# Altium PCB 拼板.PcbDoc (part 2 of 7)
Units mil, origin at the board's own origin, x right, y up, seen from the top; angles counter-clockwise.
Board outline 3630.03 x 5330.03 mil, 2 copper layers (Top Layer, Bottom Layer); 416 components, 35 nets, 1936 pads, 800 vias.
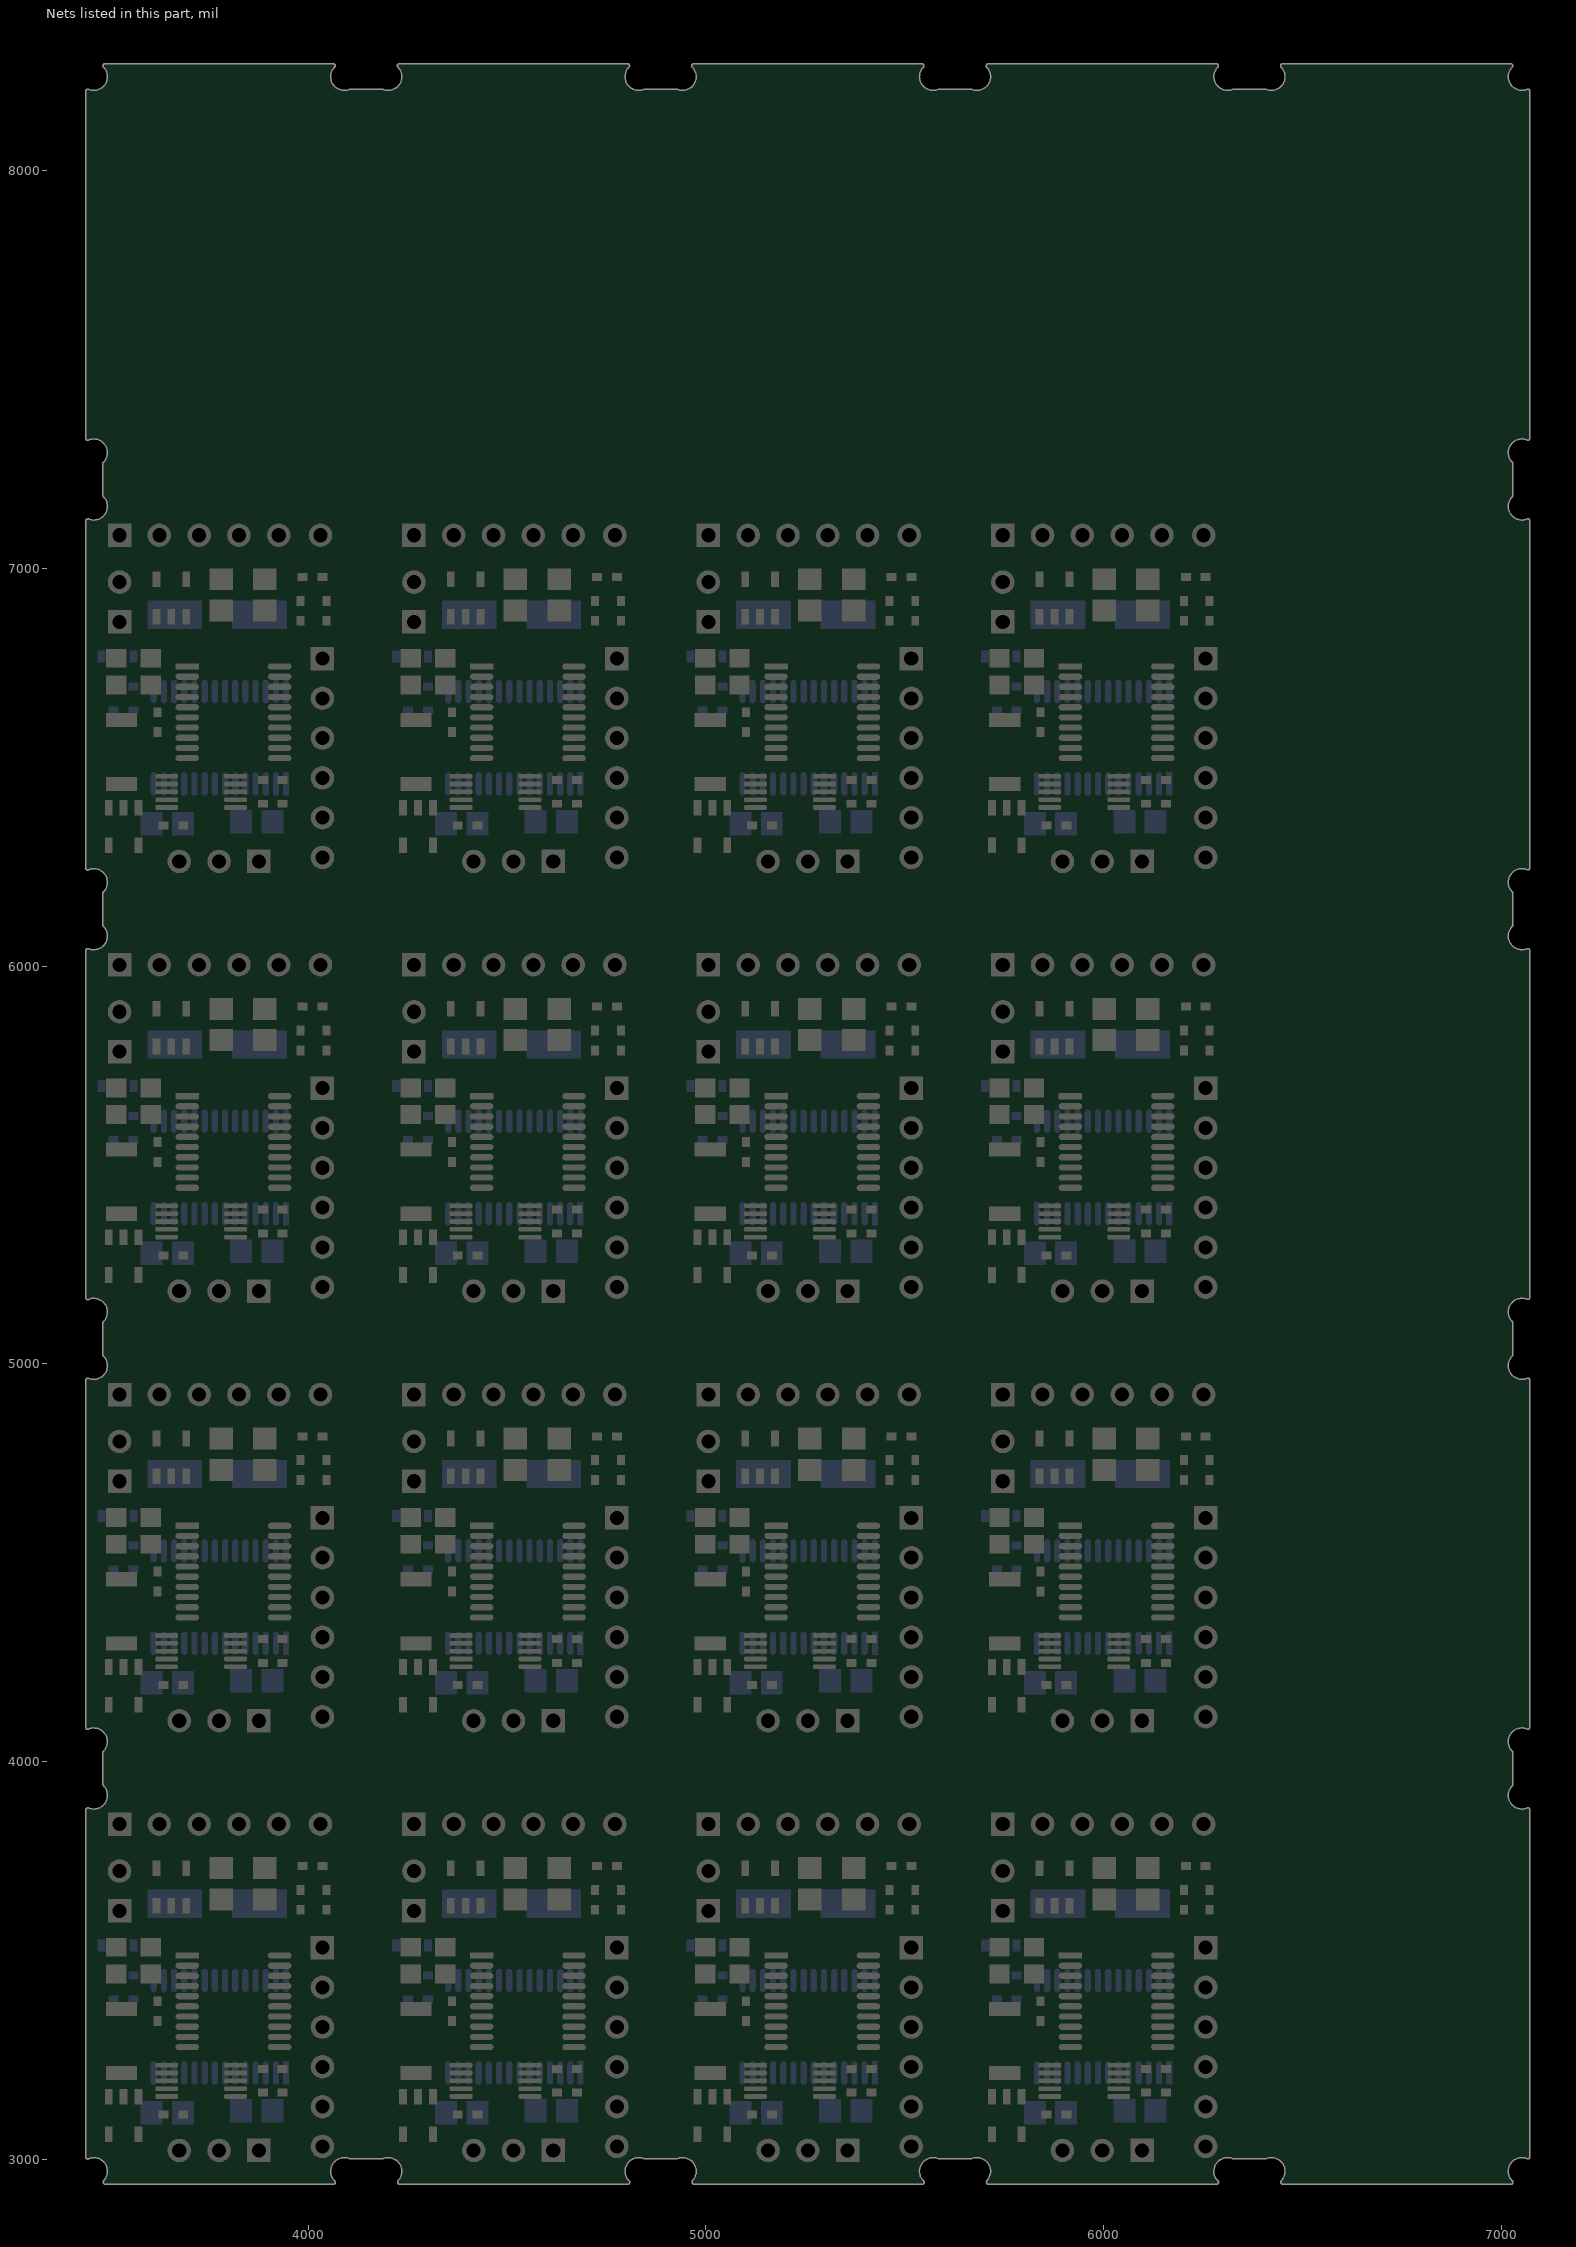
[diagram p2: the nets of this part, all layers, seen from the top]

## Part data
C011_1_1 C011_1_2 C011_1_3 C011_1_4 C011_2_1 C011_2_2 C011_2_3 C011_2_4 C011_3_1 C011_3_2 C011_3_3 C011_3_4 C011_4_1 C011_4_2 C011_4_3 C011_4_4 C021_1_1 C21_1_1 C021_1_2 C21_1_2 C021_1_3 C21_1_3 C021_1_4 C21_1_4 C021_2_1 C21_2_1 C021_2_2 C21_2_2 C021_2_3 C21_2_3 C021_2_4 C21_2_4 C021_3_1 C21_3_1 C021_3_2 C21_3_2 C021_3_3 C21_3_3 C021_3_4 C21_3_4 C021_4_1 C21_4_1 C021_4_2 C21_4_2 C021_4_3 C21_4_3 C021_4_4 C21_4_4 C22_1_1 C22_1_2 C22_1_3 C22_1_4 C22_2_1 C22_2_2 C22_2_3 C22_2_4 C22_3_1 C22_3_2 C22_3_3 C22_3_4 C22_4_1 C22_4_2 C22_4_3 C22_4_4 C23_1_1 C23_1_2 C23_1_3 C23_1_4 C23_2_1 C23_2_2 C23_2_3 C23_2_4 C23_3_1 C23_3_2 C23_3_3 C23_3_4 C23_4_1 C23_4_2 C23_4_3 C23_4_4 C24_1_1 C24_1_2 C24_1_3 C24_1_4 C24_2_1 C24_2_2 C24_2_3 C24_2_4 C24_3_1 C24_3_2 C24_3_3 C24_3_4 C24_4_1 C24_4_2 C24_4_3 C24_4_4 C051_1_1 C051_1_2 C051_1_3 C051_1_4 C051_2_1 C051_2_2 C051_2_3 C051_2_4 C051_3_1 C051_3_2 C051_3_3 C051_3_4 C051_4_1 C051_4_2 C051_4_3 C051_4_4: library part "Cap Semi", "Capacitor (Semiconductor SIM Model)"
D1_1_1 D1_1_2 D1_1_3 D1_1_4 D1_2_1 D1_2_2 D1_2_3 D1_2_4 D1_3_1 D1_3_2 D1_3_3 D1_3_4 D1_4_1 D1_4_2 D1_4_3 D1_4_4 D2_1_1 D2_1_2 D2_1_3 D2_1_4 D2_2_1 D2_2_2 D2_2_3 D2_2_4 D2_3_1 D2_3_2 D2_3_3 D2_3_4 D2_4_1 D2_4_2 D2_4_3 D2_4_4: "Default Diode"
D041_1_1 D041_1_2 D041_1_3 D041_1_4 D041_2_1 D041_2_2 D041_2_3 D041_2_4 D041_3_1 D041_3_2 D041_3_3 D041_3_4 D041_4_1 D041_4_2 D041_4_3 D041_4_4: "Typical RED, GREEN, YELLOW, AMBER GaAs LED"
P1_1_1 P1_1_2 P1_1_3 P1_1_4 P1_2_1 P1_2_2 P1_2_3 P1_2_4 P1_3_1 P1_3_2 P1_3_3 P1_3_4 P1_4_1 P1_4_2 P1_4_3 P1_4_4: "Header, 2-Pin"
P2_1_1 P2_1_2 P2_1_3 P2_1_4 P2_2_1 P2_2_2 P2_2_3 P2_2_4 P2_3_1 P2_3_2 P2_3_3 P2_3_4 P2_4_1 P2_4_2 P2_4_3 P2_4_4 P3_1_1 P3_1_2 P3_1_3 P3_1_4 P3_2_1 P3_2_2 P3_2_3 P3_2_4 P3_3_1 P3_3_2 P3_3_3 P3_3_4 P3_4_1 P3_4_2 P3_4_3 P3_4_4: "Header, 6-Pin"
P4_1_1 P4_1_2 P4_1_3 P4_1_4 P4_2_1 P4_2_2 P4_2_3 P4_2_4 P4_3_1 P4_3_2 P4_3_3 P4_3_4 P4_4_1 P4_4_2 P4_4_3 P4_4_4: "Header, 3-Pin"
R21_1_1 R21_1_2 R21_1_3 R21_1_4 R21_2_1 R21_2_2 R21_2_3 R21_2_4 R21_3_1 R21_3_2 R21_3_3 R21_3_4 R21_4_1 R21_4_2 R21_4_3 R21_4_4 R31_1_1 R31_1_2 R31_1_3 R31_1_4 R31_2_1 R31_2_2 R31_2_3 R31_2_4 R31_3_1 R31_3_2 R31_3_3 R31_3_4 R31_4_1 R31_4_2 R31_4_3 R31_4_4 R32_1_1 R32_1_2 R32_1_3 R32_1_4 R32_2_1 R32_2_2 R32_2_3 R32_2_4 R32_3_1 R32_3_2 R32_3_3 R32_3_4 R32_4_1 R32_4_2 R32_4_3 R32_4_4 R041_1_1 R041_1_2 R041_1_3 R041_1_4 R041_2_1 R041_2_2 R041_2_3 R041_2_4 R041_3_1 R041_3_2 R041_3_3 R041_3_4 R041_4_1 R041_4_2 R041_4_3 R041_4_4: "Resistor"
S051_1_1 S051_1_2 S051_1_3 S051_1_4 S051_2_1 S051_2_2 S051_2_3 S051_2_4 S051_3_1 S051_3_2 S051_3_3 S051_3_4 S051_4_1 S051_4_2 S051_4_3 S051_4_4: "Switch"

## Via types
v1: diameter 24, hole 24, Top Layer to Bottom Layer, 480 vias
v2: diameter 20, hole 10, Top Layer to Bottom Layer, 240 vias
v3: diameter 36, hole 20, Top Layer to Bottom Layer, 48 vias
v4: diameter 32, hole 16, Top Layer to Bottom Layer, 32 vias

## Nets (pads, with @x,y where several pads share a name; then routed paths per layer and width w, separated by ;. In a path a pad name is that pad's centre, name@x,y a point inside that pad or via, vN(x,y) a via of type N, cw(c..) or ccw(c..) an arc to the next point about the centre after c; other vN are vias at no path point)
1V5: 
3V3: 
ADC1_IN4: 
ADC1_IN5: 
GND: 
NetC22_2: 
NetC23_1: 
NetC24_1: 
NetC24_2: 
NetD1_1: 
NetD2_1: 
NetD041_2: 
nFAULT: 
nSLEEP: 
NSRT: 
OSC_EN: 
OSC_IN: 
OUTPUT1: 
OUTPUT2: 
OUTPUT3: 
PGND1: 
PGND3: 
SPI1_CSN: 
SPI1_MISO: 
SPI1_MOSI: 
SPI1_SCK: 
SYS_SWCLK: 
SYS_SWDIO: 
TIM3_CH1: 
TIM3_CH2: 
TIM3_CH3: 
USART1_RX: 
USART1_TX: 
VCC: 
VCC_in: 
pads on no net: C011_1_1.1 C011_1_1.2 C011_1_2.1 C011_1_2.2 C011_1_3.1 C011_1_3.2 C011_1_4.1 C011_1_4.2 C011_2_1.1 C011_2_1.2 C011_2_2.1 C011_2_2.2 C011_2_3.1 C011_2_3.2 C011_2_4.1 C011_2_4.2 C011_3_1.1 C011_3_1.2 C011_3_2.1 C011_3_2.2 C011_3_3.1 C011_3_3.2 C011_3_4.1 C011_3_4.2 C011_4_1.1 C011_4_1.2 C011_4_2.1 C011_4_2.2 C011_4_3.1 C011_4_3.2 C011_4_4.1 C011_4_4.2 C021_1_1.1 C21_1_1.1 C021_1_1.2 C21_1_1.2 C21_1_2.1 C021_1_2.1 C21_1_2.2 C021_1_2.2 C21_1_3.1 C021_1_3.1 C21_1_3.2 C021_1_3.2 C21_1_4.1 C021_1_4.1 C021_1_4.2 C21_1_4.2 C021_2_1.1 C21_2_1.1 C21_2_1.2 C021_2_1.2 C21_2_2.1 C021_2_2.1 C021_2_2.2 C21_2_2.2 C021_2_3.1 C21_2_3.1 C21_2_3.2 C021_2_3.2 C21_2_4.1 C021_2_4.1 C021_2_4.2 C21_2_4.2 C21_3_1.1 C021_3_1.1 C021_3_1.2 C21_3_1.2 C021_3_2.1 C21_3_2.1 C21_3_2.2 C021_3_2.2 C21_3_3.1 C021_3_3.1 C21_3_3.2 C021_3_3.2 C21_3_4.1 C021_3_4.1 C021_3_4.2 C21_3_4.2 C21_4_1.1 C021_4_1.1 C021_4_1.2 C21_4_1.2 C021_4_2.1 C21_4_2.1 C021_4_2.2 C21_4_2.2 C021_4_3.1 C21_4_3.1 C21_4_3.2 C021_4_3.2 C021_4_4.1 C21_4_4.1 C21_4_4.2 C021_4_4.2 C22_1_1.1 C22_1_1.2 C22_1_2.1 C22_1_2.2 C22_1_3.1 C22_1_3.2 C22_1_4.1 C22_1_4.2 C22_2_1.1 C22_2_1.2 C22_2_2.1 C22_2_2.2 C22_2_3.1 C22_2_3.2 C22_2_4.1 C22_2_4.2 C22_3_1.1 C22_3_1.2 C22_3_2.1 C22_3_2.2 C22_3_3.1 C22_3_3.2 C22_3_4.1 C22_3_4.2 C22_4_1.1 C22_4_1.2 C22_4_2.1 C22_4_2.2 C22_4_3.1 C22_4_3.2 C22_4_4.1 C22_4_4.2 C23_1_1.1 C23_1_1.2 C23_1_2.1 C23_1_2.2 C23_1_3.1 C23_1_3.2 C23_1_4.1 C23_1_4.2 C23_2_1.1 C23_2_1.2 C23_2_2.1 C23_2_2.2 C23_2_3.1 C23_2_3.2 C23_2_4.1 C23_2_4.2 C23_3_1.1 C23_3_1.2 C23_3_2.1 C23_3_2.2 C23_3_3.1 C23_3_3.2 C23_3_4.1 C23_3_4.2 C23_4_1.1 C23_4_1.2 C23_4_2.1 C23_4_2.2 C23_4_3.1 C23_4_3.2 C23_4_4.1 C23_4_4.2 C24_1_1.1 C24_1_1.2 C24_1_2.1 C24_1_2.2 C24_1_3.1 C24_1_3.2 C24_1_4.1 C24_1_4.2 C24_2_1.1 C24_2_1.2 C24_2_2.1 C24_2_2.2 C24_2_3.1 C24_2_3.2 C24_2_4.1 C24_2_4.2 C24_3_1.1 C24_3_1.2 C24_3_2.1 C24_3_2.2 C24_3_3.1 C24_3_3.2 C24_3_4.1 C24_3_4.2 C24_4_1.1 C24_4_1.2 C24_4_2.1 C24_4_2.2 C24_4_3.1 C24_4_3.2 C24_4_4.1 C24_4_4.2 C051_1_1.1 C051_1_1.2 C051_1_2.1 C051_1_2.2 C051_1_3.1 C051_1_3.2 C051_1_4.1 C051_1_4.2 C051_2_1.1 C051_2_1.2 C051_2_2.1 C051_2_2.2 C051_2_3.1 C051_2_3.2 C051_2_4.1 C051_2_4.2 C051_3_1.1 C051_3_1.2 C051_3_2.1 C051_3_2.2 C051_3_3.1 C051_3_3.2 C051_3_4.1 C051_3_4.2 C051_4_1.1 C051_4_1.2 C051_4_2.1 C051_4_2.2 C051_4_3.1 C051_4_3.2 C051_4_4.1 C051_4_4.2 con21_1_1.1 con21_1_1.2 con21_1_2.1 con21_1_2.2 con21_1_3.1 con21_1_3.2 con21_1_4.1 con21_1_4.2 con21_2_1.1 con21_2_1.2 con21_2_2.1 con21_2_2.2 con21_2_3.1 con21_2_3.2 con21_2_4.1 con21_2_4.2 con21_3_1.1 con21_3_1.2 con21_3_2.1 con21_3_2.2 con21_3_3.1 con21_3_3.2 con21_3_4.1 con21_3_4.2 con21_4_1.1 con21_4_1.2 con21_4_2.1 con21_4_2.2 con21_4_3.1 con21_4_3.2 con21_4_4.1 con21_4_4.2 D1_1_1.1 D1_1_1.2 D1_1_2.1 D1_1_2.2 D1_1_3.1 D1_1_3.2 D1_1_4.1 D1_1_4.2 D1_2_1.1 D1_2_1.2 D1_2_2.1 D1_2_2.2 D1_2_3.1 D1_2_3.2 D1_2_4.1 D1_2_4.2 D1_3_1.1 D1_3_1.2 D1_3_2.1 D1_3_2.2 D1_3_3.1 D1_3_3.2 D1_3_4.1 D1_3_4.2 D1_4_1.1 D1_4_1.2 D1_4_2.1 D1_4_2.2 D1_4_3.1 D1_4_3.2 D1_4_4.1 D1_4_4.2 D2_1_1.1 D2_1_1.2 D2_1_2.1 D2_1_2.2 D2_1_3.1 D2_1_3.2 D2_1_4.1 D2_1_4.2 D2_2_1.1 D2_2_1.2 D2_2_2.1 D2_2_2.2 D2_2_3.1 D2_2_3.2 D2_2_4.1 D2_2_4.2 D2_3_1.1 D2_3_1.2 D2_3_2.1 D2_3_2.2 D2_3_3.1 D2_3_3.2 D2_3_4.1 D2_3_4.2 D2_4_1.1 D2_4_1.2 D2_4_2.1 D2_4_2.2 D2_4_3.1 D2_4_3.2 D2_4_4.1 D2_4_4.2 D041_1_1.1 D041_1_1.2 D041_1_2.1 D041_1_2.2 D041_1_3.1 D041_1_3.2 D041_1_4.1 D041_1_4.2 D041_2_1.1 D041_2_1.2 D041_2_2.1 D041_2_2.2 D041_2_3.1 D041_2_3.2 D041_2_4.1 D041_2_4.2 D041_3_1.1 D041_3_1.2 D041_3_2.1 D041_3_2.2 D041_3_3.1 D041_3_3.2 D041_3_4.1 D041_3_4.2 D041_4_1.1 D041_4_1.2 D041_4_2.1 D041_4_2.2 D041_4_3.1 D041_4_3.2 D041_4_4.1 D041_4_4.2 P1_1_1.1 P1_1_1.2 P1_1_2.1 P1_1_2.2 P1_1_3.1 P1_1_3.2 P1_1_4.1 P1_1_4.2 P1_2_1.1 P1_2_1.2 P1_2_2.1 P1_2_2.2 P1_2_3.1 P1_2_3.2 P1_2_4.1 P1_2_4.2 P1_3_1.1 P1_3_1.2 P1_3_2.1 P1_3_2.2 P1_3_3.1 P1_3_3.2 P1_3_4.1 P1_3_4.2 P1_4_1.1 P1_4_1.2 P1_4_2.1 P1_4_2.2 P1_4_3.1 P1_4_3.2 P1_4_4.1 P1_4_4.2 P2_1_1.1 P2_1_1.2 P2_1_1.3 P2_1_1.4 P2_1_1.5 P2_1_1.6 P2_1_2.1 P2_1_2.2 P2_1_2.3 P2_1_2.4 P2_1_2.5 P2_1_2.6 P2_1_3.1 P2_1_3.2 P2_1_3.3 P2_1_3.4 P2_1_3.5 P2_1_3.6 P2_1_4.1 P2_1_4.2 P2_1_4.3 P2_1_4.4 P2_1_4.5 P2_1_4.6 P2_2_1.1 P2_2_1.2 P2_2_1.3 P2_2_1.4 P2_2_1.5 P2_2_1.6 P2_2_2.1 P2_2_2.2 P2_2_2.3 P2_2_2.4 P2_2_2.5 P2_2_2.6 P2_2_3.1 P2_2_3.2 P2_2_3.3 P2_2_3.4 P2_2_3.5 P2_2_3.6 P2_2_4.1 P2_2_4.2 P2_2_4.3 P2_2_4.4 P2_2_4.5 P2_2_4.6 P2_3_1.1 P2_3_1.2 P2_3_1.3 P2_3_1.4 P2_3_1.5 P2_3_1.6 P2_3_2.1 P2_3_2.2 P2_3_2.3 P2_3_2.4 P2_3_2.5 P2_3_2.6 P2_3_3.1 P2_3_3.2 P2_3_3.3 P2_3_3.4 P2_3_3.5 P2_3_3.6 P2_3_4.1 P2_3_4.2 P2_3_4.3 P2_3_4.4 P2_3_4.5 P2_3_4.6 P2_4_1.1 P2_4_1.2 P2_4_1.3 P2_4_1.4 P2_4_1.5 P2_4_1.6 P2_4_2.1 P2_4_2.2 P2_4_2.3 P2_4_2.4 P2_4_2.5 P2_4_2.6 P2_4_3.1 P2_4_3.2 P2_4_3.3 P2_4_3.4 P2_4_3.5 P2_4_3.6 P2_4_4.1 P2_4_4.2 P2_4_4.3 P2_4_4.4 P2_4_4.5 P2_4_4.6 P3_1_1.1 P3_1_1.2 P3_1_1.3 P3_1_1.4 P3_1_1.5 P3_1_1.6 P3_1_2.1 P3_1_2.2 P3_1_2.3 P3_1_2.4 P3_1_2.5 P3_1_2.6 P3_1_3.1 P3_1_3.2 P3_1_3.3 P3_1_3.4 P3_1_3.5 P3_1_3.6 P3_1_4.1 P3_1_4.2 P3_1_4.3 P3_1_4.4 P3_1_4.5 P3_1_4.6 P3_2_1.1 P3_2_1.2 P3_2_1.3 P3_2_1.4 P3_2_1.5 P3_2_1.6 P3_2_2.1 P3_2_2.2 P3_2_2.3 P3_2_2.4 P3_2_2.5 P3_2_2.6 P3_2_3.1 P3_2_3.2 P3_2_3.3 P3_2_3.4 P3_2_3.5 P3_2_3.6 P3_2_4.1 P3_2_4.2 P3_2_4.3 P3_2_4.4 P3_2_4.5 P3_2_4.6 P3_3_1.1 P3_3_1.2 P3_3_1.3 P3_3_1.4 P3_3_1.5 P3_3_1.6 P3_3_2.1 P3_3_2.2 P3_3_2.3 P3_3_2.4 P3_3_2.5 P3_3_2.6 P3_3_3.1 P3_3_3.2 P3_3_3.3 P3_3_3.4 P3_3_3.5 P3_3_3.6 P3_3_4.1 P3_3_4.2 P3_3_4.3 P3_3_4.4 P3_3_4.5 P3_3_4.6 P3_4_1.1 P3_4_1.2 P3_4_1.3 P3_4_1.4 P3_4_1.5 P3_4_1.6 P3_4_2.1 P3_4_2.2 P3_4_2.3 P3_4_2.4 P3_4_2.5 P3_4_2.6 P3_4_3.1 P3_4_3.2 P3_4_3.3 P3_4_3.4 P3_4_3.5 P3_4_3.6 P3_4_4.1 P3_4_4.2 P3_4_4.3 P3_4_4.4 P3_4_4.5 P3_4_4.6 P4_1_1.1 P4_1_1.2 P4_1_1.3 P4_1_2.1 P4_1_2.2 P4_1_2.3 P4_1_3.1 P4_1_3.2 P4_1_3.3 P4_1_4.1 P4_1_4.2 P4_1_4.3 P4_2_1.1 P4_2_1.2 P4_2_1.3 P4_2_2.1 P4_2_2.2 P4_2_2.3 P4_2_3.1 P4_2_3.2 P4_2_3.3 P4_2_4.1 P4_2_4.2 P4_2_4.3 P4_3_1.1 P4_3_1.2 P4_3_1.3 P4_3_2.1 P4_3_2.2 P4_3_2.3 P4_3_3.1 P4_3_3.2 P4_3_3.3 P4_3_4.1 P4_3_4.2 P4_3_4.3 P4_4_1.1 P4_4_1.2 P4_4_1.3 P4_4_2.1 P4_4_2.2 P4_4_2.3 P4_4_3.1 P4_4_3.2 P4_4_3.3 P4_4_4.1 P4_4_4.2 P4_4_4.3 R21_1_1.1 R21_1_1.2 R21_1_2.1 R21_1_2.2 R21_1_3.1 R21_1_3.2 R21_1_4.1 R21_1_4.2 R21_2_1.1 R21_2_1.2 R21_2_2.1 R21_2_2.2 R21_2_3.1 R21_2_3.2 R21_2_4.1 R21_2_4.2 R21_3_1.1 R21_3_1.2 R21_3_2.1 R21_3_2.2 R21_3_3.1 R21_3_3.2 R21_3_4.1 R21_3_4.2 R21_4_1.1 R21_4_1.2 R21_4_2.1 R21_4_2.2 R21_4_3.1 R21_4_3.2 R21_4_4.1 R21_4_4.2 R31_1_1.1 R31_1_1.2 R31_1_2.1 R31_1_2.2 R31_1_3.1 R31_1_3.2 R31_1_4.1 R31_1_4.2 R31_2_1.1 R31_2_1.2 R31_2_2.1 R31_2_2.2 R31_2_3.1 R31_2_3.2 R31_2_4.1 R31_2_4.2 R31_3_1.1 R31_3_1.2 R31_3_2.1 R31_3_2.2 R31_3_3.1 R31_3_3.2 R31_3_4.1 R31_3_4.2 R31_4_1.1 R31_4_1.2 R31_4_2.1 R31_4_2.2 R31_4_3.1 R31_4_3.2 R31_4_4.1 R31_4_4.2 R32_1_1.1 R32_1_1.2 R32_1_2.1 R32_1_2.2 R32_1_3.1 R32_1_3.2 R32_1_4.1 R32_1_4.2 R32_2_1.1 R32_2_1.2 R32_2_2.1 R32_2_2.2 R32_2_3.1 R32_2_3.2 R32_2_4.1 R32_2_4.2 R32_3_1.1 R32_3_1.2 R32_3_2.1 R32_3_2.2 R32_3_3.1 R32_3_3.2 R32_3_4.1 R32_3_4.2 R32_4_1.1 R32_4_1.2 R32_4_2.1 R32_4_2.2 R32_4_3.1 R32_4_3.2 R32_4_4.1 R32_4_4.2 R041_1_1.1 R041_1_1.2 R041_1_2.1 R041_1_2.2 R041_1_3.1 R041_1_3.2 R041_1_4.1 R041_1_4.2 R041_2_1.1 R041_2_1.2 R041_2_2.1 R041_2_2.2 R041_2_3.1 R041_2_3.2 R041_2_4.1 R041_2_4.2 R041_3_1.1 R041_3_1.2 R041_3_2.1 R041_3_2.2 R041_3_3.1 R041_3_3.2 R041_3_4.1 R041_3_4.2 R041_4_1.1 R041_4_1.2 R041_4_2.1 R041_4_2.2 R041_4_3.1 R041_4_3.2 R041_4_4.1 R041_4_4.2 S051_1_1.1 S051_1_1.2 S051_1_2.1 S051_1_2.2 S051_1_3.1 S051_1_3.2 S051_1_4.1 S051_1_4.2 S051_2_1.1 S051_2_1.2 S051_2_2.1 S051_2_2.2 S051_2_3.1 S051_2_3.2 S051_2_4.1 S051_2_4.2 S051_3_1.1 S051_3_1.2 S051_3_2.1 S051_3_2.2 S051_3_3.1 S051_3_3.2 S051_3_4.1 S051_3_4.2 S051_4_1.1 S051_4_1.2 S051_4_2.1 S051_4_2.2 S051_4_3.1 S051_4_3.2 S051_4_4.1 S051_4_4.2 U1_1_1.1 U01_1_1.1 U1_1_1.2 U01_1_1.2 U01_1_1.3 U1_1_1.3 U1_1_1.4 U01_1_1.4 U01_1_1.5 U1_1_1.5 U1_1_1.6 U1_1_1.7 U1_1_1.8 U1_1_1.9 U1_1_1.10 U1_1_1.11 U1_1_1.12 U1_1_1.13 U1_1_1.14 U1_1_1.15 U1_1_1.16 U1_1_1.17 U1_1_1.18 U1_1_1.19 U1_1_1.20 U1_1_2.1 U01_1_2.1 U01_1_2.2 U1_1_2.2 U01_1_2.3 U1_1_2.3 U01_1_2.4 U1_1_2.4 U01_1_2.5 U1_1_2.5 U1_1_2.6 U1_1_2.7 U1_1_2.8 U1_1_2.9 U1_1_2.10 U1_1_2.11 U1_1_2.12 U1_1_2.13 U1_1_2.14 U1_1_2.15 U1_1_2.16 U1_1_2.17 U1_1_2.18 U1_1_2.19 U1_1_2.20 U1_1_3.1 U01_1_3.1 U1_1_3.2 U01_1_3.2 U01_1_3.3 U1_1_3.3 U1_1_3.4 U01_1_3.4 U01_1_3.5 U1_1_3.5 U1_1_3.6 U1_1_3.7 U1_1_3.8 U1_1_3.9 U1_1_3.10 U1_1_3.11 U1_1_3.12 U1_1_3.13 U1_1_3.14 U1_1_3.15 U1_1_3.16 U1_1_3.17 U1_1_3.18 U1_1_3.19 U1_1_3.20 U1_1_4.1 U01_1_4.1 U01_1_4.2 U1_1_4.2 U01_1_4.3 U1_1_4.3 U1_1_4.4 U01_1_4.4 U01_1_4.5 U1_1_4.5 U1_1_4.6 U1_1_4.7 U1_1_4.8 U1_1_4.9 U1_1_4.10 U1_1_4.11 U1_1_4.12 U1_1_4.13 U1_1_4.14 U1_1_4.15 U1_1_4.16 U1_1_4.17 U1_1_4.18 U1_1_4.19 U1_1_4.20 U01_2_1.1 U1_2_1.1 U01_2_1.2 U1_2_1.2 U1_2_1.3 U01_2_1.3 U1_2_1.4 U01_2_1.4 U01_2_1.5 U1_2_1.5 U1_2_1.6 U1_2_1.7 U1_2_1.8 U1_2_1.9 U1_2_1.10 U1_2_1.11 U1_2_1.12 U1_2_1.13 U1_2_1.14 U1_2_1.15 U1_2_1.16 U1_2_1.17 U1_2_1.18 U1_2_1.19 U1_2_1.20 U01_2_2.1 U1_2_2.1 U01_2_2.2 U1_2_2.2 U01_2_2.3 U1_2_2.3 U1_2_2.4 U01_2_2.4 U01_2_2.5 U1_2_2.5 U1_2_2.6 U1_2_2.7 U1_2_2.8 U1_2_2.9 U1_2_2.10 U1_2_2.11 U1_2_2.12 U1_2_2.13 U1_2_2.14 U1_2_2.15 U1_2_2.16 U1_2_2.17 U1_2_2.18 U1_2_2.19 U1_2_2.20 U01_2_3.1 U1_2_3.1 U1_2_3.2 U01_2_3.2 U01_2_3.3 U1_2_3.3 U1_2_3.4 U01_2_3.4 U01_2_3.5 U1_2_3.5 U1_2_3.6 U1_2_3.7 U1_2_3.8 U1_2_3.9 U1_2_3.10 U1_2_3.11 U1_2_3.12 U1_2_3.13 U1_2_3.14 U1_2_3.15 U1_2_3.16 U1_2_3.17 U1_2_3.18 U1_2_3.19 U1_2_3.20 U1_2_4.1 U01_2_4.1 U01_2_4.2 U1_2_4.2 U1_2_4.3 U01_2_4.3 U01_2_4.4 U1_2_4.4 U1_2_4.5 U01_2_4.5 U1_2_4.6 U1_2_4.7 U1_2_4.8 U1_2_4.9 U1_2_4.10 U1_2_4.11 U1_2_4.12 U1_2_4.13 U1_2_4.14 U1_2_4.15 U1_2_4.16 U1_2_4.17 U1_2_4.18 U1_2_4.19 U1_2_4.20 U1_3_1.1 U01_3_1.1 U1_3_1.2 U01_3_1.2 U1_3_1.3 U01_3_1.3 U01_3_1.4 U1_3_1.4 U01_3_1.5 U1_3_1.5 U1_3_1.6 U1_3_1.7 U1_3_1.8 U1_3_1.9 U1_3_1.10 U1_3_1.11 U1_3_1.12 U1_3_1.13 U1_3_1.14 U1_3_1.15 U1_3_1.16 U1_3_1.17 U1_3_1.18 U1_3_1.19 U1_3_1.20 U01_3_2.1 U1_3_2.1 U1_3_2.2 U01_3_2.2 U1_3_2.3 U01_3_2.3 U01_3_2.4 U1_3_2.4 U1_3_2.5 U01_3_2.5 U1_3_2.6 U1_3_2.7 U1_3_2.8 U1_3_2.9 U1_3_2.10 U1_3_2.11 U1_3_2.12 U1_3_2.13 U1_3_2.14 U1_3_2.15 U1_3_2.16 U1_3_2.17 U1_3_2.18 U1_3_2.19 U1_3_2.20 U1_3_3.1 U01_3_3.1 U1_3_3.2 U01_3_3.2 U01_3_3.3 U1_3_3.3 U1_3_3.4 U01_3_3.4 U01_3_3.5 U1_3_3.5 U1_3_3.6 U1_3_3.7 U1_3_3.8 U1_3_3.9 U1_3_3.10 U1_3_3.11 U1_3_3.12 U1_3_3.13 U1_3_3.14 U1_3_3.15 U1_3_3.16 U1_3_3.17 U1_3_3.18 U1_3_3.19 U1_3_3.20 U01_3_4.1 U1_3_4.1 U1_3_4.2 U01_3_4.2 U1_3_4.3 U01_3_4.3 U1_3_4.4 U01_3_4.4 U01_3_4.5 U1_3_4.5 U1_3_4.6 U1_3_4.7 U1_3_4.8 U1_3_4.9 U1_3_4.10 U1_3_4.11 U1_3_4.12 U1_3_4.13 U1_3_4.14 U1_3_4.15 U1_3_4.16 U1_3_4.17 U1_3_4.18 U1_3_4.19 U1_3_4.20 U01_4_1.1 U1_4_1.1 U1_4_1.2 U01_4_1.2 U1_4_1.3 U01_4_1.3 U01_4_1.4 U1_4_1.4 U01_4_1.5 U1_4_1.5 U1_4_1.6 U1_4_1.7 U1_4_1.8 U1_4_1.9 U1_4_1.10 U1_4_1.11 U1_4_1.12 U1_4_1.13 U1_4_1.14 U1_4_1.15 U1_4_1.16 U1_4_1.17 U1_4_1.18 U1_4_1.19 U1_4_1.20 U1_4_2.1 U01_4_2.1 U01_4_2.2 U1_4_2.2 U1_4_2.3 U01_4_2.3 U1_4_2.4 U01_4_2.4 U1_4_2.5 U01_4_2.5 U1_4_2.6 U1_4_2.7 U1_4_2.8 U1_4_2.9 U1_4_2.10 U1_4_2.11 U1_4_2.12 U1_4_2.13 U1_4_2.14 U1_4_2.15 U1_4_2.16 U1_4_2.17 U1_4_2.18 U1_4_2.19 U1_4_2.20 U01_4_3.1 U1_4_3.1 U01_4_3.2 U1_4_3.2 U01_4_3.3 U1_4_3.3 U01_4_3.4 U1_4_3.4 U01_4_3.5 U1_4_3.5 U1_4_3.6 U1_4_3.7 U1_4_3.8 U1_4_3.9 U1_4_3.10 U1_4_3.11 U1_4_3.12 U1_4_3.13 U1_4_3.14 U1_4_3.15 U1_4_3.16 U1_4_3.17 U1_4_3.18 U1_4_3.19 U1_4_3.20 U01_4_4.1 U1_4_4.1 U01_4_4.2 U1_4_4.2 U01_4_4.3 U1_4_4.3 U01_4_4.4 U1_4_4.4 U01_4_4.5 U1_4_4.5 U1_4_4.6 U1_4_4.7 U1_4_4.8 U1_4_4.9 U1_4_4.10 U1_4_4.11 U1_4_4.12 U1_4_4.13 U1_4_4.14 U1_4_4.15 U1_4_4.16 U1_4_4.17 U1_4_4.18 U1_4_4.19 U1_4_4.20 u02_1_1.1 U02_1_1.1 U2_1_1.1 u02_1_1.2 U2_1_1.2 U02_1_1.2 U2_1_1.3 U02_1_1.3 u02_1_1.3 U02_1_1.4 u02_1_1.4 U2_1_1.4 U2_1_1.5 u02_1_1.5 U2_1_1.6 U2_1_1.7 U2_1_1.8 U2_1_1.9 U2_1_1.10 U2_1_1.11 U2_1_1.12 U2_1_1.13 U2_1_1.14 U2_1_1.15 U2_1_1.16 U2_1_1.17 U2_1_1.18 U2_1_1.19 U2_1_1.20 U2_1_1.21 U2_1_1.22 U2_1_1.23 U2_1_1.24 U2_1_1.25 U2_1_1.26 U2_1_1.27 U2_1_1.28 U2_1_2.1 U02_1_2.1 u02_1_2.1 U2_1_2.2 U02_1_2.2 u02_1_2.2 U02_1_2.3 U2_1_2.3 u02_1_2.3 u02_1_2.4 U02_1_2.4 U2_1_2.4 u02_1_2.5 U2_1_2.5 U2_1_2.6 U2_1_2.7 U2_1_2.8 U2_1_2.9 U2_1_2.10 U2_1_2.11 U2_1_2.12 U2_1_2.13 U2_1_2.14 U2_1_2.15 U2_1_2.16 U2_1_2.17 U2_1_2.18 U2_1_2.19 U2_1_2.20 U2_1_2.21 U2_1_2.22 U2_1_2.23 U2_1_2.24 U2_1_2.25 U2_1_2.26 U2_1_2.27 U2_1_2.28 U02_1_3.1 u02_1_3.1 U2_1_3.1 u02_1_3.2 U02_1_3.2 U2_1_3.2 u02_1_3.3 U2_1_3.3 U02_1_3.3 U02_1_3.4 U2_1_3.4 u02_1_3.4 U2_1_3.5 u02_1_3.5 U2_1_3.6 U2_1_3.7 U2_1_3.8 U2_1_3.9 U2_1_3.10 U2_1_3.11 U2_1_3.12 U2_1_3.13 U2_1_3.14 U2_1_3.15 U2_1_3.16 U2_1_3.17 U2_1_3.18 U2_1_3.19 U2_1_3.20 U2_1_3.21 U2_1_3.22 U2_1_3.23 U2_1_3.24 U2_1_3.25 U2_1_3.26 U2_1_3.27 U2_1_3.28 u02_1_4.1 U02_1_4.1 U2_1_4.1 U02_1_4.2 U2_1_4.2 u02_1_4.2 u02_1_4.3 U02_1_4.3 U2_1_4.3 u02_1_4.4 U2_1_4.4 U02_1_4.4 U2_1_4.5 u02_1_4.5 U2_1_4.6 U2_1_4.7 U2_1_4.8 U2_1_4.9 U2_1_4.10 U2_1_4.11 U2_1_4.12 U2_1_4.13 U2_1_4.14 U2_1_4.15 U2_1_4.16 U2_1_4.17 U2_1_4.18 U2_1_4.19 U2_1_4.20 U2_1_4.21 U2_1_4.22 U2_1_4.23 U2_1_4.24 U2_1_4.25 U2_1_4.26 U2_1_4.27 U2_1_4.28 U02_2_1.1 U2_2_1.1 u02_2_1.1 u02_2_1.2 U02_2_1.2 U2_2_1.2 u02_2_1.3 U02_2_1.3 U2_2_1.3 U02_2_1.4 u02_2_1.4 U2_2_1.4 u02_2_1.5 U2_2_1.5 U2_2_1.6 U2_2_1.7 U2_2_1.8 U2_2_1.9 U2_2_1.10 U2_2_1.11 U2_2_1.12 U2_2_1.13 U2_2_1.14 U2_2_1.15 U2_2_1.16 U2_2_1.17 U2_2_1.18 U2_2_1.19 U2_2_1.20 U2_2_1.21 U2_2_1.22 U2_2_1.23 U2_2_1.24 U2_2_1.25 U2_2_1.26 U2_2_1.27 U2_2_1.28 U2_2_2.1 U02_2_2.1 u02_2_2.1 U2_2_2.2 U02_2_2.2 u02_2_2.2 U02_2_2.3 U2_2_2.3 u02_2_2.3 u02_2_2.4 U02_2_2.4 U2_2_2.4 U2_2_2.5 u02_2_2.5 U2_2_2.6 U2_2_2.7 U2_2_2.8 U2_2_2.9 U2_2_2.10 U2_2_2.11 U2_2_2.12 U2_2_2.13 U2_2_2.14 U2_2_2.15 U2_2_2.16 U2_2_2.17 U2_2_2.18 U2_2_2.19 U2_2_2.20 U2_2_2.21 U2_2_2.22 U2_2_2.23 U2_2_2.24 U2_2_2.25 U2_2_2.26 U2_2_2.27 U2_2_2.28 U2_2_3.1 u02_2_3.1 U02_2_3.1 U2_2_3.2 u02_2_3.2 U02_2_3.2 U02_2_3.3 u02_2_3.3 U2_2_3.3 u02_2_3.4 U02_2_3.4 U2_2_3.4 u02_2_3.5 U2_2_3.5 U2_2_3.6 U2_2_3.7 U2_2_3.8 U2_2_3.9 U2_2_3.10 U2_2_3.11 U2_2_3.12 U2_2_3.13 U2_2_3.14 U2_2_3.15 U2_2_3.16 U2_2_3.17 U2_2_3.18 U2_2_3.19 U2_2_3.20 U2_2_3.21 U2_2_3.22 U2_2_3.23 U2_2_3.24 U2_2_3.25 U2_2_3.26 U2_2_3.27 U2_2_3.28 U02_2_4.1 U2_2_4.1 u02_2_4.1 U2_2_4.2 U02_2_4.2 u02_2_4.2 U2_2_4.3 u02_2_4.3 U02_2_4.3 U2_2_4.4 u02_2_4.4 U02_2_4.4 u02_2_4.5 U2_2_4.5 U2_2_4.6 U2_2_4.7 U2_2_4.8 U2_2_4.9 U2_2_4.10 U2_2_4.11 U2_2_4.12 U2_2_4.13 U2_2_4.14 U2_2_4.15 U2_2_4.16 U2_2_4.17 U2_2_4.18 U2_2_4.19 U2_2_4.20 U2_2_4.21 U2_2_4.22 U2_2_4.23 U2_2_4.24 U2_2_4.25 U2_2_4.26 U2_2_4.27 U2_2_4.28 u02_3_1.1 U02_3_1.1 U2_3_1.1 U2_3_1.2 u02_3_1.2 U02_3_1.2 U2_3_1.3 U02_3_1.3 u02_3_1.3 U2_3_1.4 u02_3_1.4 U02_3_1.4 u02_3_1.5 U2_3_1.5 U2_3_1.6 U2_3_1.7 U2_3_1.8 U2_3_1.9 U2_3_1.10 U2_3_1.11 U2_3_1.12 U2_3_1.13 U2_3_1.14 U2_3_1.15 U2_3_1.16 U2_3_1.17 U2_3_1.18 U2_3_1.19 U2_3_1.20 U2_3_1.21 U2_3_1.22 U2_3_1.23 U2_3_1.24 U2_3_1.25 U2_3_1.26 U2_3_1.27 U2_3_1.28 U2_3_2.1 u02_3_2.1 U02_3_2.1 u02_3_2.2 U2_3_2.2 U02_3_2.2 u02_3_2.3 U02_3_2.3 U2_3_2.3 U02_3_2.4 u02_3_2.4 U2_3_2.4 u02_3_2.5 U2_3_2.5 U2_3_2.6 U2_3_2.7 U2_3_2.8 U2_3_2.9 U2_3_2.10 U2_3_2.11 U2_3_2.12 U2_3_2.13 U2_3_2.14 U2_3_2.15 U2_3_2.16 U2_3_2.17 U2_3_2.18 U2_3_2.19 U2_3_2.20 U2_3_2.21 U2_3_2.22 U2_3_2.23 U2_3_2.24 U2_3_2.25 U2_3_2.26 U2_3_2.27 U2_3_2.28 u02_3_3.1 U02_3_3.1 U2_3_3.1 U02_3_3.2 u02_3_3.2 U2_3_3.2 U2_3_3.3 U02_3_3.3 u02_3_3.3 U02_3_3.4 u02_3_3.4 U2_3_3.4 U2_3_3.5 u02_3_3.5 U2_3_3.6 U2_3_3.7 U2_3_3.8 U2_3_3.9 U2_3_3.10 U2_3_3.11 U2_3_3.12 U2_3_3.13 U2_3_3.14 U2_3_3.15 U2_3_3.16 U2_3_3.17 U2_3_3.18 U2_3_3.19 U2_3_3.20 U2_3_3.21 U2_3_3.22 U2_3_3.23 U2_3_3.24 U2_3_3.25 U2_3_3.26 U2_3_3.27 U2_3_3.28 u02_3_4.1 U2_3_4.1 U02_3_4.1 u02_3_4.2 U2_3_4.2 U02_3_4.2 U2_3_4.3 U02_3_4.3 u02_3_4.3 u02_3_4.4 U02_3_4.4 U2_3_4.4 u02_3_4.5 U2_3_4.5 U2_3_4.6 U2_3_4.7 U2_3_4.8 U2_3_4.9 U2_3_4.10 U2_3_4.11 U2_3_4.12 U2_3_4.13 U2_3_4.14 U2_3_4.15 U2_3_4.16 U2_3_4.17 U2_3_4.18 U2_3_4.19 U2_3_4.20 U2_3_4.21 U2_3_4.22 U2_3_4.23 U2_3_4.24 U2_3_4.25 U2_3_4.26 U2_3_4.27 U2_3_4.28 U02_4_1.1 u02_4_1.1 U2_4_1.1 U02_4_1.2 U2_4_1.2 u02_4_1.2 U2_4_1.3 u02_4_1.3 U02_4_1.3 U02_4_1.4 U2_4_1.4 u02_4_1.4 U2_4_1.5 u02_4_1.5 U2_4_1.6 U2_4_1.7 U2_4_1.8 U2_4_1.9 U2_4_1.10 U2_4_1.11 U2_4_1.12 U2_4_1.13 U2_4_1.14 U2_4_1.15 U2_4_1.16 U2_4_1.17 U2_4_1.18 U2_4_1.19 U2_4_1.20 U2_4_1.21 U2_4_1.22 U2_4_1.23 U2_4_1.24 U2_4_1.25 U2_4_1.26 U2_4_1.27 U2_4_1.28 U02_4_2.1 u02_4_2.1 U2_4_2.1 U02_4_2.2 U2_4_2.2 u02_4_2.2 u02_4_2.3 U02_4_2.3 U2_4_2.3 U02_4_2.4 U2_4_2.4 u02_4_2.4 U2_4_2.5 u02_4_2.5 U2_4_2.6 U2_4_2.7 U2_4_2.8 U2_4_2.9 U2_4_2.10 U2_4_2.11 U2_4_2.12 U2_4_2.13 U2_4_2.14 U2_4_2.15 U2_4_2.16 U2_4_2.17 U2_4_2.18 U2_4_2.19 U2_4_2.20 U2_4_2.21 U2_4_2.22 U2_4_2.23 U2_4_2.24 U2_4_2.25 U2_4_2.26 U2_4_2.27 U2_4_2.28 u02_4_3.1 U2_4_3.1 U02_4_3.1 U02_4_3.2 u02_4_3.2 U2_4_3.2 u02_4_3.3 U02_4_3.3 U2_4_3.3 U2_4_3.4 u02_4_3.4 U02_4_3.4 u02_4_3.5 U2_4_3.5 U2_4_3.6 U2_4_3.7 U2_4_3.8 U2_4_3.9 U2_4_3.10 U2_4_3.11 U2_4_3.12 U2_4_3.13 U2_4_3.14 U2_4_3.15 U2_4_3.16 U2_4_3.17 U2_4_3.18 U2_4_3.19 U2_4_3.20 U2_4_3.21 U2_4_3.22 U2_4_3.23 U2_4_3.24 U2_4_3.25 U2_4_3.26 U2_4_3.27 U2_4_3.28 U2_4_4.1 U02_4_4.1 u02_4_4.1 U2_4_4.2 U02_4_4.2 u02_4_4.2 U02_4_4.3 U2_4_4.3 u02_4_4.3 u02_4_4.4 U02_4_4.4 U2_4_4.4 U2_4_4.5 u02_4_4.5 U2_4_4.6 U2_4_4.7 U2_4_4.8 U2_4_4.9 U2_4_4.10 U2_4_4.11 U2_4_4.12 U2_4_4.13 U2_4_4.14 U2_4_4.15 U2_4_4.16 U2_4_4.17 U2_4_4.18 U2_4_4.19 U2_4_4.20 U2_4_4.21 U2_4_4.22 U2_4_4.23 U2_4_4.24 U2_4_4.25 U2_4_4.26 U2_4_4.27 U2_4_4.28 U3_1_1.1 U3_1_1.2 U3_1_1.3 U3_1_1.4 U3_1_1.5 U3_1_1.6 U3_1_1.7 U3_1_1.8 U3_1_1.9 U3_1_1.10 U3_1_2.1 U3_1_2.2 U3_1_2.3 U3_1_2.4 U3_1_2.5 U3_1_2.6 U3_1_2.7 U3_1_2.8 U3_1_2.9 U3_1_2.10 U3_1_3.1 U3_1_3.2 U3_1_3.3 U3_1_3.4 U3_1_3.5 U3_1_3.6 U3_1_3.7 U3_1_3.8 U3_1_3.9 U3_1_3.10 U3_1_4.1 U3_1_4.2 U3_1_4.3 U3_1_4.4 U3_1_4.5 U3_1_4.6 U3_1_4.7 U3_1_4.8 U3_1_4.9 U3_1_4.10 U3_2_1.1 U3_2_1.2 U3_2_1.3 U3_2_1.4 U3_2_1.5 U3_2_1.6 U3_2_1.7 U3_2_1.8 U3_2_1.9 U3_2_1.10 U3_2_2.1 U3_2_2.2 U3_2_2.3 U3_2_2.4 U3_2_2.5 U3_2_2.6 U3_2_2.7 U3_2_2.8 U3_2_2.9 U3_2_2.10 U3_2_3.1 U3_2_3.2 U3_2_3.3 U3_2_3.4 U3_2_3.5 U3_2_3.6 U3_2_3.7 U3_2_3.8 U3_2_3.9 U3_2_3.10 U3_2_4.1 U3_2_4.2 U3_2_4.3 U3_2_4.4 U3_2_4.5 U3_2_4.6 U3_2_4.7 U3_2_4.8 U3_2_4.9 U3_2_4.10 U3_3_1.1 U3_3_1.2 U3_3_1.3 U3_3_1.4 U3_3_1.5 U3_3_1.6 U3_3_1.7 U3_3_1.8 U3_3_1.9 U3_3_1.10 U3_3_2.1 U3_3_2.2 U3_3_2.3 U3_3_2.4 U3_3_2.5 U3_3_2.6 U3_3_2.7 U3_3_2.8 U3_3_2.9 U3_3_2.10 U3_3_3.1 U3_3_3.2 U3_3_3.3 U3_3_3.4 U3_3_3.5 U3_3_3.6 U3_3_3.7 U3_3_3.8 U3_3_3.9 U3_3_3.10 U3_3_4.1 U3_3_4.2 U3_3_4.3 U3_3_4.4 U3_3_4.5 U3_3_4.6 U3_3_4.7 U3_3_4.8 U3_3_4.9 U3_3_4.10 U3_4_1.1 U3_4_1.2 U3_4_1.3 U3_4_1.4 U3_4_1.5 U3_4_1.6 U3_4_1.7 U3_4_1.8 U3_4_1.9 U3_4_1.10 U3_4_2.1 U3_4_2.2 U3_4_2.3 U3_4_2.4 U3_4_2.5 U3_4_2.6 U3_4_2.7 U3_4_2.8 U3_4_2.9 U3_4_2.10 U3_4_3.1 U3_4_3.2 U3_4_3.3 U3_4_3.4 U3_4_3.5 U3_4_3.6 U3_4_3.7 U3_4_3.8 U3_4_3.9 U3_4_3.10 U3_4_4.1 U3_4_4.2 U3_4_4.3 U3_4_4.4 U3_4_4.5 U3_4_4.6 U3_4_4.7 U3_4_4.8 U3_4_4.9 U3_4_4.10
